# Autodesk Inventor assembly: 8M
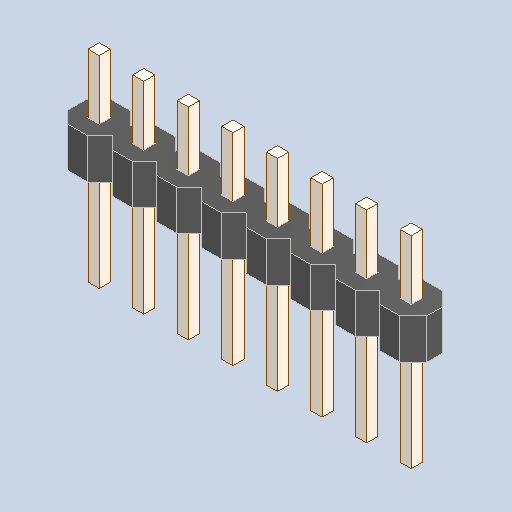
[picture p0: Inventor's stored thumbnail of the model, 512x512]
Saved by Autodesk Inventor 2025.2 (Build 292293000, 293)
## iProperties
Created: 2025-04
Part Number: 8M
Description: PART--DESC
Document SubType Name: Assembly
Designer: BennF
Author: BennF
Revision Number: NONE
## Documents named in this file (3)
- C:\Users\BennF\Nextcloud\Benutzer\CNC JarBeRi\existing parts\Electronics\RepRap A4988 Shied (USE WITHOUT ARDUINO)\reprap-a4988-1.snapshot.1\RepRap\RepRap\8M_3.iam
- C:\Users\BennF\Nextcloud\Benutzer\CNC JarBeRi\existing parts\Electronics\RepRap A4988 Shied (USE WITHOUT ARDUINO)\reprap-a4988-1.snapshot.1\RepRap\RepRap\8M Geometry.ipt
- C:\Users\BennF\Nextcloud\Benutzer\CNC JarBeRi\existing parts\Electronics\RepRap A4988 Shied (USE WITHOUT ARDUINO)\reprap-a4988-1.snapshot.1\RepRap\RepRap\pin4.ipt
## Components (2 placed, 2 different names)
1. 8M Geometry
2. pin4
